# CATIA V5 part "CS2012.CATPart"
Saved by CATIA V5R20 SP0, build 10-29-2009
Part number: CS2012
Revision: 5
Definition: design
Nomenclature: CS2012
Source: made
Description: NOT SPECIFIED
Bounding box of the stored display mesh (mm): x -11.818 to 12, y -12 to 12, z -22 to 6
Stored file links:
  C:\Users\Raffaele\Desktop\3D X SITO CF\BOLEX\20-TILTED COLUMN SUPPORT\CS2012.CATPart
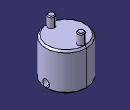
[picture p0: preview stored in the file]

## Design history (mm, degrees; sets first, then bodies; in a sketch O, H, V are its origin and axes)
Body1 "MANIFOLD_SOLID_BREP #685" (main body)
  Solid1: solid without history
